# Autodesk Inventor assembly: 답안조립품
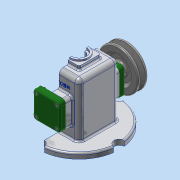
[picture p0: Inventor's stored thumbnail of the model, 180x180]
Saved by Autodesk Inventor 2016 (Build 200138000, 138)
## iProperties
Created: 2018-07
Part Number: 답안조립품
Material: 일반
Document SubType Name: Assembly
Designer: 605-03
Author: 605-03
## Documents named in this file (12)
- C:\Users\605-03\Desktop\480707V1003\답안조립품.iam
- C:\Users\605-03\Desktop\480707V1003\본체.ipt
- C:\Users\605-03\Desktop\480707V1003\편심축.ipt
- C:\Users\605-03\Desktop\480707V1003\베어링 12x32x10.ipt
- C:\Users\605-03\Desktop\480707V1003\앞커버.ipt
- C:\Users\605-03\Desktop\480707V1003\뒤커버.ipt
- C:\Users\605-03\Desktop\480707V1003\오일 실 12 25 7.ipt
- C:\Users\605-03\Desktop\480707V1003\링크.ipt
- C:\Users\605-03\Desktop\480707V1003\V벨트풀리.ipt
- C:\Users\605-03\Desktop\480707V1003\키 4x4x10.ipt
- C:\Users\605-03\Desktop\480707V1003\멈춤나사 M3x8.ipt
- C:\Users\605-03\Desktop\480707V1003\볼트 M4.ipt
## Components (1 placed, 1 different names)
1. V벨트풀리:1
